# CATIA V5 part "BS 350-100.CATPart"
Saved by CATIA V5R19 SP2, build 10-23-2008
Part number: BS 300-100
Bounding box of the stored display mesh (mm): x -15.868 to 15.868, y -15.868 to 15.868, z 0 to 230
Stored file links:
  C:\Users\Bora\Desktop\3D Katı model\BS serisi\BS 300\BS 300-100.CATPart
  C:\Program Files\Dassault Systemes\B19\intel_a\reffiles\standard\MetricThickPitch.txt
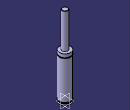
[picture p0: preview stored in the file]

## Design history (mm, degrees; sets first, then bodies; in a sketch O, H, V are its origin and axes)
Body1 (main body)
  Sketch1 on yz-plane, origin (0, 0, 0), H (0, 1, 0), V (0, 0, 1)
    point P1 (8, 229)
    point P3 (8, 229)
    point P5 (16, 119.5)
    point P6 (16, 117.5)
    point P9 (16, 119.5)
    point P14 (16, 117.5)
    line L1 (8, 229) -> (8, 129)
    arc A1 centre (7, 229) radius 1 from (8, 229) to (7, 230) ccw
    arc A2 centre (16, 118.5) radius 1 from (16, 119.5) to (16, 117.5) ccw
    line L2 (16, 0) -> (16, 4)
    line L3 (16, 119.5) -> (16, 129)
    line L4 (14.5, 7.5) -> (14.5, 4)
    line L5 (16, 7.5) -> (16, 117.5)
    line L6 (7, 230) -> (0, 230)
    point P15 (0, 230)
    line L7 (8, 129) -> (16, 129)
    line L8 (0, 0) -> (16, 0)
    line L9 (14.5, 7.5) -> (16, 7.5)
    line L10 (14.5, 4) -> (16, 4)
    coincidence: P15 V, P1 P3, P5 P9, P6 P14
    tangency: L6 A1
    horizontal: L7 H, L8 H, L9 H, L10 H
  Shaft1: profile Sketch1, axis Sketch1.V, angle 360
  Sketch2 on face of Shaft1 from Sketch1.L8, origin (0, 0, 0), H (1, 0, 0), V (0, -1, 0)
    point P1 (0, 0)
  Hole1: placed by Sketch2, at (0, 0, 0) direction (0, 0, 1), diameter 6.647, depth 4, threaded "M8", thread diameter 8, thread depth 4, pitch 1.25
